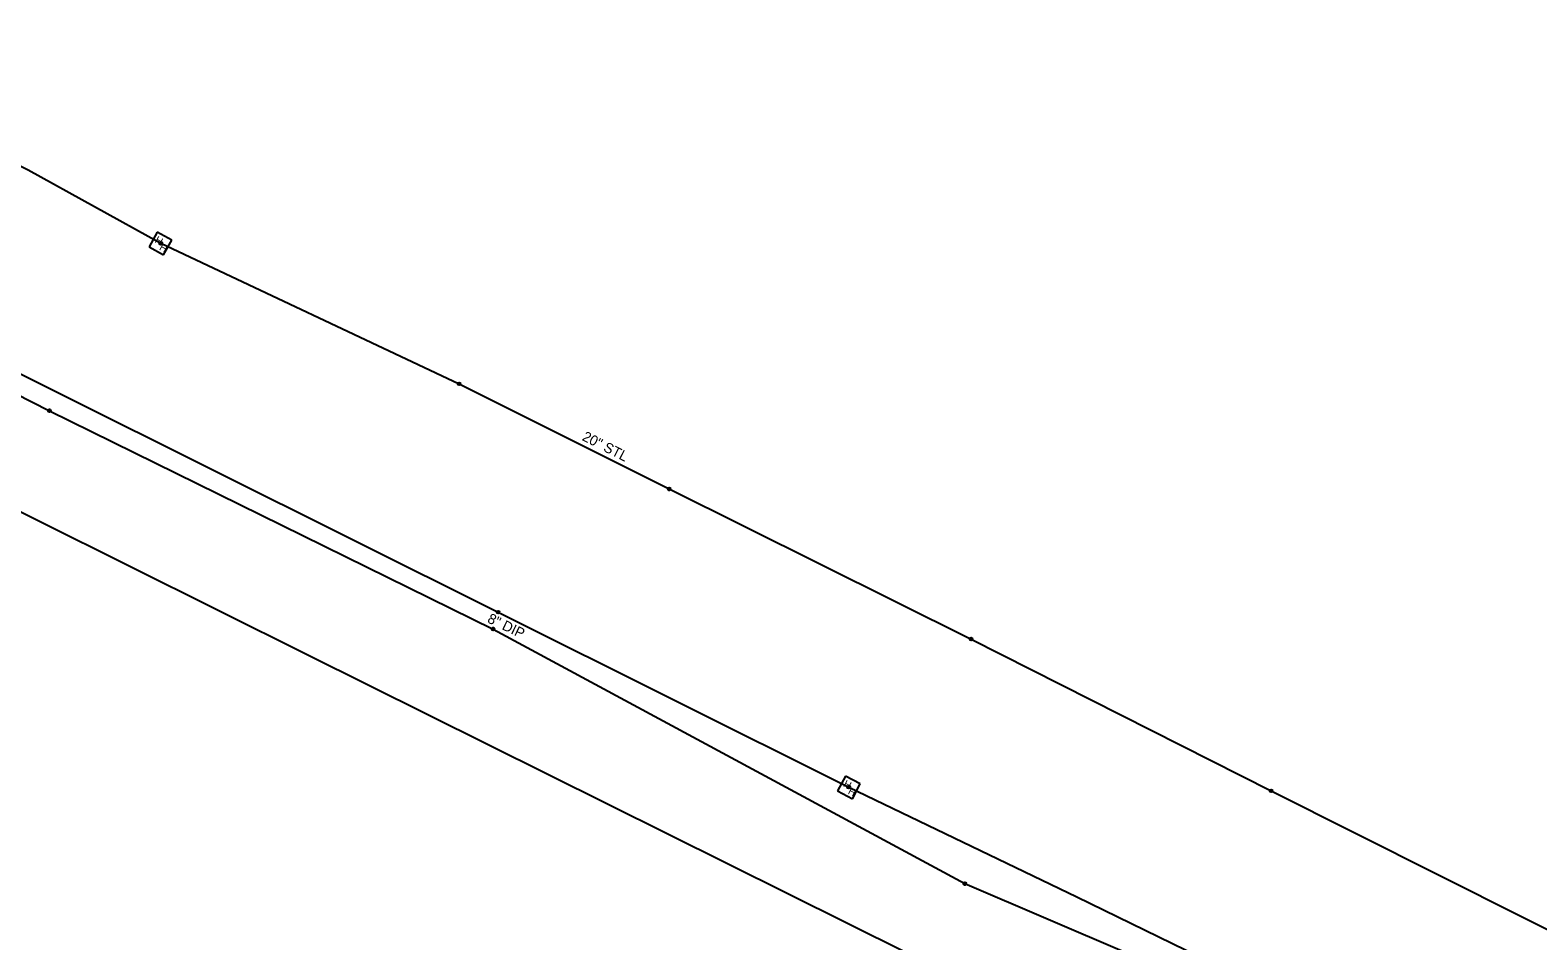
# Model space of a CAD drawing. Extents: x 2244485 to 2250986, y 199568 to 203007.
# Drawn here: x 2248328 to 2248846, y 200876 to 201189 of the extents above; entities that cross this region are included whole.
import ezdxf

# ---------------------------------------------------------------- set-up
doc = ezdxf.new("R2010")
doc.units = 0
for name, color, linetype in [('Default', 7, 'Continuous'), ('Exist Utilities Gas Meter CELL', 7, 'Continuous'), ('Exist Utilities Gas UG Line SUE LOS B', 7, 'Continuous'), ('Exist Utilities Gas UG Line SUE LOS B Text', 7, 'Continuous'), ('Exist Utilities Sanitary Sewer Forced Main SUE LOS B', 7, 'Continuous'), ('Exist Utilities Sanitary Sewer Forced Main SUE LOS B Text', 7, 'Continuous'), ('Exist Utilities Telephone Hand Hole CELL', 7, 'Continuous'), ('Exist Utilities Telephone UG Cable SUE LOS C', 7, 'Continuous'), ('Exist Utilities Telephone UG FO SUE LOS B', 7, 'Continuous')]:
    doc.layers.add(name, color=color, linetype=linetype)

# ---------------------------------------------------------------- blocks, each defined once
blk = doc.blocks.new('SurveyPointCell')
at = {"layer": 'Default'}
for p, q in [((-0.5, 0), (0.5, 0)), ((0, -0.5), (0, 0.5))]:
    blk.add_line(p, q, dxfattribs=at)
blk.add_circle((0, 0), 0.5, dxfattribs=at)

msp = doc.modelspace()

# ---------------------------------------------------------------- linework, layer by layer
at = {"layer": 'Exist Utilities Gas Meter CELL'}
for p, q in [((2248371.81, 201119.47), (2248369.04, 201114.45)), ((2248376.82, 201116.7), (2248371.81, 201119.47)), ((2248372.93, 201115.58), (2248372.93, 201115.58)), ((2248374.05, 201111.69), (2248376.82, 201116.7)), ((2248369.04, 201114.45), (2248374.05, 201111.69))]:
    msp.add_line(p, q, dxfattribs=at)
at = {"layer": 'Exist Utilities Gas UG Line SUE LOS B'}
msp.add_lwpolyline([(2247602.4, 201501.88), (2247749.1, 201426.01), (2247995.53, 201302.57), (2248159.78, 201224.66), (2248327.53, 201140.85), (2248373.07, 201115.64), (2248475.56, 201067.34), (2248547.65, 201031.24), (2248651.39, 200979.65), (2248754.41, 200927.49), (2248898.77, 200854.93), (2249046.68, 200783.06), (2249166.77, 200725.47), (2249287.36, 200663.03), (2249402.68, 200604.16)], dxfattribs=at)
at = {"layer": 'Exist Utilities Sanitary Sewer Forced Main SUE LOS B'}
msp.add_lwpolyline([(2247735.41, 201350.67), (2247801.59, 201317.51), (2247922.39, 201259.82), (2248074.17, 201183.48), (2248161.38, 201141.9), (2248228.53, 201112.29), (2248334.87, 201058.12), (2248487.25, 200983.06), (2248649.22, 200895.6), (2248733.43, 200859.57), (2248875.85, 200789.39), (2249055.92, 200697.85), (2249217.76, 200621.23), (2249370.62, 200544.89)], dxfattribs=at)
at = {"layer": 'Exist Utilities Telephone Hand Hole CELL'}
for p, q in [((2248608.21, 200932.52), (2248605.53, 200927.46)), ((2248613.27, 200929.84), (2248608.21, 200932.52)), ((2248610.59, 200924.78), (2248613.27, 200929.84)), ((2248605.53, 200927.46), (2248610.59, 200924.78)), ((2248609.4, 200928.65), (2248609.4, 200928.65))]:
    msp.add_line(p, q, dxfattribs=at)
at = {"layer": 'Exist Utilities Telephone UG Cable SUE LOS C'}
msp.add_lwpolyline([(2248238.7, 201066.28), (2248423.59, 200974.24), (2248773.82, 200799.99), (2248835.88, 200770.97), (2248854.39, 200763.25), (2248860.78, 200766.45), (2248866.15, 200773.75), (2248880.19, 200799.94), (2248868.48, 200773.69), (2248865.46, 200766.31), (2248865.37, 200759.63), (2248891.36, 200747.54), (2249235.17, 200571.04), (2249362.52, 200506.1), (2249646.99, 200363.79)], dxfattribs=at)
at = {"layer": 'Exist Utilities Telephone UG FO SUE LOS B'}
msp.add_lwpolyline([(2247734.6, 201364.13), (2247798.15, 201331.66), (2247859.88, 201301.14), (2247925.6, 201269.67), (2247988.72, 201238.28), (2248114.06, 201176.6), (2248183.16, 201141.53), (2248221.91, 201121.81), (2248290.07, 201088.12), (2248488.94, 200988.89), (2248609.32, 200928.77), (2248687.7, 200891.02), (2248748.44, 200861.37), (2248829.89, 200822.11), (2248864.68, 200804.04), (2248883.46, 200794.42), (2248944.92, 200764.27), (2249005.82, 200733.82), (2249066.5, 200704.1), (2249128.64, 200672.91), (2249190.46, 200641.51), (2249254.14, 200610.49), (2249321.49, 200578.44), (2249387.5, 200544.86)], dxfattribs=at)

# ---------------------------------------------------------------- block references
at = {"layer": 'Default'}
for p in [(2248373.07, 201115.64), (2248475.56, 201067.34), (2248334.87, 201058.12), (2248547.65, 201031.24), (2248488.94, 200988.89), (2248487.25, 200983.06), (2248651.39, 200979.65), (2248609.32, 200928.77), (2248754.41, 200927.49), (2248649.22, 200895.6)]:
    msp.add_blockref('SurveyPointCell', p, dxfattribs=at)

# ---------------------------------------------------------------- texts
at = {"layer": 'Exist Utilities Gas Meter CELL'}
for p in [(2248370.82, 201116.07), (2248372.36, 201113.54)]:
    msp.add_text('H', height=2.5, rotation=331.0771, dxfattribs=at).set_placement(p)
at = {"layer": 'Exist Utilities Gas UG Line SUE LOS B Text'}
msp.add_text('20" STL', height=3.5, rotation=333.0915, dxfattribs=at).set_placement((2248517.51, 201048.11))
at = {"layer": 'Exist Utilities Sanitary Sewer Forced Main SUE LOS B Text'}
msp.add_text('8" DIP', height=3.5, rotation=334.4319, dxfattribs=at).set_placement((2248484.96, 200985.49))
at = {"layer": 'Exist Utilities Telephone Hand Hole CELL'}
for p in [(2248607.28, 200929.1), (2248608.86, 200926.6)]:
    msp.add_text('H', height=2.5, rotation=332.0893, dxfattribs=at).set_placement(p)

doc.saveas('drawing.dxf')
